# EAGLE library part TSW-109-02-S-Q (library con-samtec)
THROUGH-HOLE .025" SQ POST HEADER Source: Samtec TSW.pdf
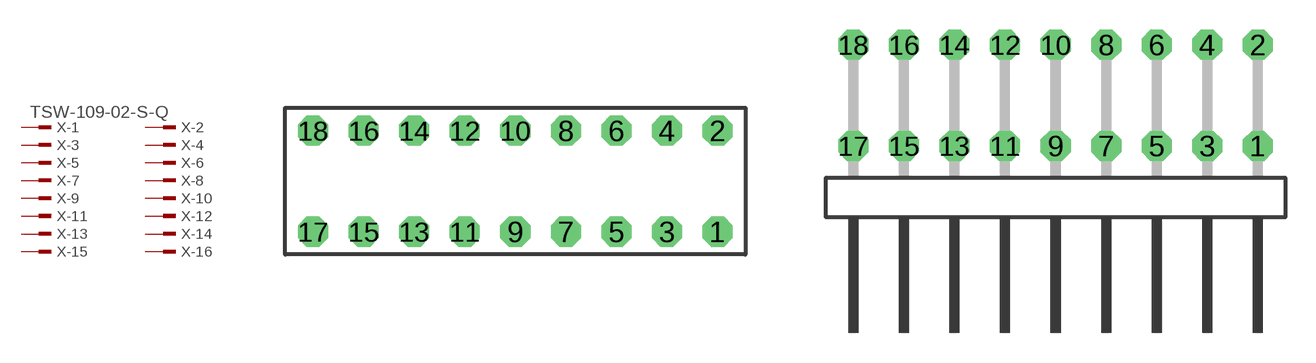
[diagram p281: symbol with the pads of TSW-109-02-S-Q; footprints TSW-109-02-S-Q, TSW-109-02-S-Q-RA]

Designator prefix X; gates -1=MPINV -2=MPIN -3=MPIN -4=MPIN -5=MPIN -6=MPIN -7=MPIN -8=MPIN -9=MPIN -10=MPIN -11=MPIN -12=MPIN -13=MPIN -14=MPIN -15=MPIN -16=MPIN -17=MPIN -18=MPIN

## TSW-109-02-S-Q (OC_FARNELL: unknown; OC_NEWARK: unknown)  [TSW-109-02-S-Q]
1  -1:1  pas
2  -2:1  pas
3  -3:1  pas
4  -4:1  pas
5  -5:1  pas
6  -6:1  pas
7  -7:1  pas
8  -8:1  pas
9  -9:1  pas
10  -10:1  pas
11  -11:1  pas
12  -12:1  pas
13  -13:1  pas
14  -14:1  pas
15  -15:1  pas
16  -16:1  pas
17  -17:1  pas
18  -18:1  pas

## TSW-109-02-S-Q-RA (OC_FARNELL: unknown; OC_NEWARK: unknown)  [TSW-109-02-S-Q-RA]
Pads as for TSW-109-02-S-Q

## Footprint TSW-109-02-S-Q (pad centres in mm)
THROUGH-HOLE .025" SQ POST HEADER Source: Samtec TSW.pdf
drill 1 pad 1.5 octagon: 1 10.16,-2.54; 2 10.16,2.54; 3 7.62,-2.54; 4 7.62,2.54; 5 5.08,-2.54; 6 5.08,2.54; 7 2.54,-2.54; 8 2.54,2.54; 9 0,-2.54; 10 0,2.54; 11 -2.54,-2.54; 12 -2.54,2.54; 13 -5.08,-2.54; 14 -5.08,2.54; 15 -7.62,-2.54; 16 -7.62,2.54; 17 -10.16,-2.54; 18 -10.16,2.54

## Footprint TSW-109-02-S-Q-RA (pad centres in mm)
THROUGH-HOLE .025" SQ POST HEADER Source: Samtec TSW.pdf
drill 1 pad 1.5 octagon: 1 10.16,1.524; 2 10.16,6.604; 3 7.62,1.524; 4 7.62,6.604; 5 5.08,1.524; 6 5.08,6.604; 7 2.54,1.524; 8 2.54,6.604; 9 0,1.524; 10 0,6.604; 11 -2.54,1.524; 12 -2.54,6.604; 13 -5.08,1.524; 14 -5.08,6.604; 15 -7.62,1.524; 16 -7.62,6.604; 17 -10.16,1.524; 18 -10.16,6.604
